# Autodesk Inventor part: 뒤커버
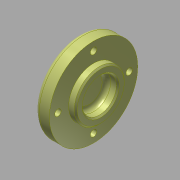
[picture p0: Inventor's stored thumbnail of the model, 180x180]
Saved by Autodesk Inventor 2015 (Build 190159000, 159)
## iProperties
Created: 2015-12
Part Number: 뒤커버
Document SubType Name: Modeling
Designer: mdu
Density: 2.71 g/cm^3
Material: 알루미늄 6061
Mass: 80.8084 g
Surface Area: 93.036 cm^2
Volume: 29.8186 cm^3
Appearance: 알루미늄 - 평지
Author: mdu
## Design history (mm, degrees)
sketch "스케치1"
  geometry: L1 (-7.5, 0)-(7.5, 0); L2 (-7.5, 0)-(-7.5, 31); L3 (-7.5, 31)-(2.5, 31); L4 (2.5, 31)-(2.5, 17.5); L5 (2.5, 17.5)-(7.5, 17.5); L6 (7.5, 17.5)-(7.5, 0); 2 further points
  constraints: 12 end point, 3 parallel, 1 coincident, 1 horizontal, 1 midpoint, 1 perpendicular
  dimensions: "d0" = 15 distance of L1.start L1.end; "d1" = 62 diameter of L3 L1; "d2" = 35 diameter of L5 L1; "d34" = 10 distance of L2.end L3.end
revolve "회전1" sketch "스케치1" stored, may be unused: angle "d6" = 90 deg
sketch "스케치2" dims "d32" = 50
  geometry: 3 further points
  constraints: 2 vertical alignment, 1 coincident, 2 other
hole "구멍1" sketch "스케치2" at (0, 25) diameter "d8" = 4.5; stored, may be unused: countersink angle "d12" = 90 deg, drill point angle "d14" = 118 deg; dims "d9" = 6, "d10" = 8, "d11" = 4.4, "d13" = 8
hole "구멍2" diameter "d20" = 24; stored, may be unused: countersink angle "d24" = 90 deg, drill point angle "d26" = 0 deg; dims "d18" = 10, "d19" = 10, "d21" = 6, "d22" = 8, "d23" = 4.4, "d25" = 8
fillet "모깎기1" dims "d27" = 3
fillet "모깎기2" dims "d28" = 3
chamfer "모따기1" distance "d29" = 1; stored, may be unused: second distance "d30" = 2, angle "d31" = 45 deg
node "솔리드1"
pattern_circular "원형 패턴1" dims angle "d16" = 360 deg
